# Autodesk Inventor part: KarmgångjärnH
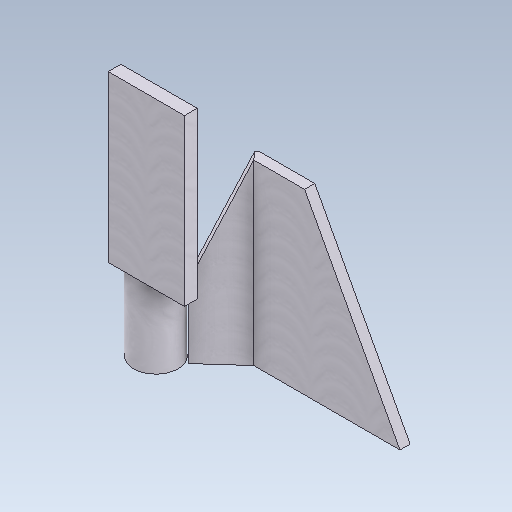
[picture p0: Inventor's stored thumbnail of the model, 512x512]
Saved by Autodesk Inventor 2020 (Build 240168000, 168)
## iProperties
Created: 2019-06
Part Number: KarmgångjärnH
Material: Aluminum 6061, Welded
Document SubType Name: Modeling
Designer: cl
Density: 2.7 g/cm^3
Appearance: Weld - Aluminum
Author: cl
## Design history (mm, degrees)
sketch "Sketch1"
  geometry: L1 (0, 8)-(115, 8); L2 (118.071, 0)-(0, 0); L3 (0, 0)-(0, 8); L4 (115, 8)-(142.016, 32.325); L5 (115, 8)-(126.561, 8); L6 (118.071, 0)-(147.369, 26.38); L7 (142.016, 32.325)-(147.369, 26.38); C1 r 17.5 at (160, 40); 2 further points
  constraints: 14 end point, 2 coincident, 2 horizontal, 2 parallel, 1 centre point, 1 vertical
  dimensions: "d0" = 35 diameter of C1; "d1" = 40 vertical distance of point (0, 0) C1.centre; "d2" = 160 horizontal distance of point (0, 0) C1.centre; "d3" = 42 deg angle of L5 L4; "d4" = 8 distance between parallel lines of L4 L6; "d5" = 8 distance between parallel lines of L1 L2; "d6" = 115 horizontal distance of point (0, 0) L1.end; "d7" = 1 distance edge to line of C1 L7; "d8" = 90 deg angle of L4 L7; "d10" = 27.76238 distance from line of L5.end L7
extrude "Extrusion1" new body sketch "Sketch1" distance "d11" = 140; taper "d12" = 0 deg
thicken "Thicken1" dims "d13" = 10, "d14" = 80
chamfer "Chamfer1" distance "d15" = 140; stored, may be unused: second distance "d16" = 75, angle "d17" = 45 deg
sketch "Sketch2"
  geometry: L1 (-36.354, 140)-(-66.079, 140) reference; L2 (-36.354, 140)-(0, 56); L3 (0, 0)-(0, 140) reference; L4 (0, 140)-(-36.354, 140) reference; L5 (0, 56)-(0, 140); L6 (0, 140)-(-36.354, 140); 1 further point
  constraints: 6 end point, 1 perpendicular, 1 point on line, 1 vertical
  dimensions: "d18" = 56 distance of L3.start L2.end
extrude "Extrusion2" cut sketch "Sketch2" extent not by distance; stored distance "d19" = 29.794; taper "d20" = 0 deg
workplane "Work Plane1"
sketch "Sketch3"
  geometry: L1 (-57.5, 200)-(2.5, 200); L2 (2.5, 200)-(2.5, 70); L3 (2.5, 70)-(-57.5, 70); L4 (-57.5, 70)-(-57.5, 200); L5 (-62.5, 130)-(-27.5, 130) reference; L6 (-27.5, 0)-(-62.5, 0) reference; 1 further point
  constraints: 8 end point, 2 parallel, 1 horizontal, 1 perpendicular
  dimensions: "d22" = 5 distance from line of L5.start L4; "d23" = 60 distance of L1.start L1.end; "d24" = 130 distance of L3.end L1.start; "d25" = 70 distance between parallel lines of L1 L5
extrude "Extrusion3" join sketch "Sketch3" distance "d26" = 10; taper "d27" = 0 deg
body "Solid1"
node "Projected Loop1"
other parameters: "d21" = 57
